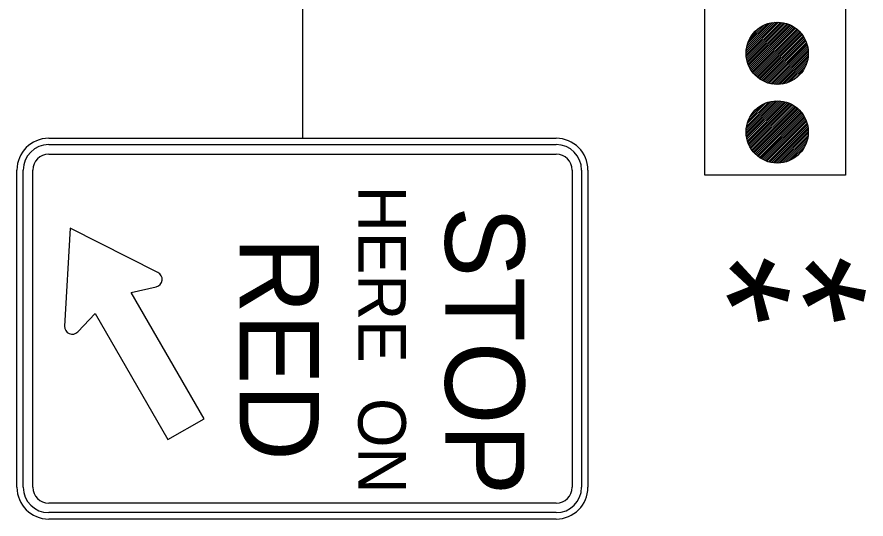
# Model space of a CAD drawing. Extents: x 1927831 to 1930787, y 596452 to 597699.
# Drawn here: x 1928583.7 to 1928664, y 597412.1 to 597459.5 of the extents above; entities that cross this region are included whole.
import ezdxf

# ---------------------------------------------------------------- set-up
doc = ezdxf.new("R2010")
doc.units = 0
for name, color, linetype in [('Default', 7, 'Continuous'), ('P_TC_Signs_Permanent', 7, 'Continuous'), ('R_Border', 7, 'Continuous')]:
    doc.layers.add(name, color=color, linetype=linetype)

msp = doc.modelspace()

# ---------------------------------------------------------------- linework, layer by layer
at = {"layer": 'Default'}
for p, q in [((1928652.681, 597456.132), (1928655.58, 597459.031)), ((1928652.684, 597455.954), (1928655.758, 597459.028)), ((1928652.69, 597456.321), (1928655.391, 597459.022)), ((1928652.697, 597455.785), (1928655.927, 597459.015)), ((1928652.714, 597456.526), (1928655.186, 597458.998)), ((1928652.718, 597455.625), (1928656.087, 597458.994)), ((1928652.746, 597455.473), (1928656.239, 597458.966)), ((1928652.756, 597456.749), (1928654.963, 597458.956)), ((1928652.782, 597455.327), (1928656.385, 597458.93)), ((1928652.823, 597455.188), (1928656.524, 597458.889)), ((1928652.825, 597456.999), (1928654.713, 597458.887)), ((1928652.869, 597455.053), (1928656.659, 597458.842)), ((1928652.921, 597454.925), (1928656.787, 597458.791)), ((1928652.939, 597457.294), (1928654.418, 597458.773)), ((1928652.978, 597454.801), (1928656.911, 597458.734)), ((1928653.04, 597454.681), (1928657.031, 597458.672)), ((1928653.106, 597454.566), (1928657.146, 597458.606)), ((1928653.156, 597457.691), (1928654.021, 597458.556)), ((1928653.176, 597454.456), (1928657.256, 597458.536)), ((1928653.251, 597454.349), (1928657.363, 597458.461)), ((1928653.329, 597454.247), (1928657.465, 597458.383)), ((1928653.412, 597454.149), (1928657.563, 597458.3)), ((1928653.498, 597454.054), (1928657.658, 597458.214)), ((1928653.589, 597453.964), (1928657.748, 597458.123)), ((1928653.683, 597453.877), (1928657.835, 597458.029)), ((1928653.782, 597453.795), (1928657.917, 597457.93)), ((1928653.884, 597453.716), (1928657.996, 597457.828)), ((1928653.99, 597453.642), (1928658.07, 597457.722)), ((1928654.101, 597453.572), (1928658.14, 597457.611)), ((1928654.216, 597453.506), (1928658.206, 597457.496)), ((1928654.335, 597453.444), (1928658.268, 597457.377)), ((1928654.459, 597453.387), (1928658.325, 597457.253)), ((1928654.588, 597453.335), (1928658.377, 597457.124)), ((1928654.722, 597453.289), (1928658.423, 597456.99)), ((1928654.862, 597453.248), (1928658.464, 597456.85)), ((1928655.008, 597453.212), (1928658.5, 597456.704)), ((1928655.16, 597453.184), (1928658.528, 597456.552)), ((1928655.32, 597453.163), (1928658.549, 597456.392)), ((1928655.489, 597453.151), (1928658.561, 597456.223)), ((1928655.667, 597453.148), (1928658.564, 597456.045)), ((1928655.857, 597453.157), (1928658.555, 597455.855)), ((1928656.061, 597453.18), (1928658.532, 597455.651)), ((1928656.285, 597453.223), (1928658.489, 597455.427)), ((1928656.535, 597453.293), (1928658.419, 597455.177)), ((1928656.83, 597453.407), (1928658.305, 597454.882)), ((1928657.229, 597453.625), (1928658.087, 597454.483)), ((1928652.681, 597448.612), (1928655.661, 597451.592)), ((1928652.685, 597448.797), (1928655.476, 597451.588)), ((1928652.689, 597448.439), (1928655.834, 597451.584)), ((1928652.701, 597448.994), (1928655.279, 597451.572)), ((1928652.705, 597448.274), (1928655.998, 597451.568)), ((1928652.73, 597448.118), (1928656.155, 597451.543)), ((1928652.735, 597449.208), (1928655.065, 597451.538)), ((1928652.761, 597447.969), (1928656.304, 597451.512)), ((1928652.791, 597449.445), (1928654.828, 597451.482)), ((1928652.799, 597447.826), (1928656.447, 597451.474)), ((1928652.843, 597447.688), (1928656.584, 597451.43)), ((1928652.881, 597449.717), (1928654.556, 597451.392)), ((1928652.892, 597447.557), (1928656.716, 597451.381)), ((1928652.946, 597447.43), (1928656.843, 597451.327)), ((1928653.005, 597447.308), (1928656.965, 597451.268)), ((1928653.038, 597450.054), (1928654.219, 597451.235)), ((1928653.069, 597447.191), (1928657.082, 597451.204)), ((1928653.137, 597447.078), (1928657.195, 597451.136)), ((1928653.209, 597446.969), (1928657.304, 597451.064)), ((1928653.285, 597446.865), (1928657.408, 597450.988)), ((1928653.365, 597446.764), (1928657.509, 597450.908)), ((1928653.45, 597446.667), (1928657.606, 597450.823)), ((1928653.538, 597446.575), (1928657.698, 597450.735)), ((1928653.63, 597446.486), (1928657.787, 597450.643)), ((1928653.726, 597446.401), (1928657.872, 597450.547)), ((1928653.826, 597446.321), (1928657.952, 597450.446)), ((1928653.931, 597446.244), (1928658.029, 597450.342)), ((1928654.039, 597446.171), (1928658.102, 597450.234)), ((1928654.151, 597446.103), (1928658.17, 597450.122)), ((1928654.268, 597446.039), (1928658.234, 597450.005)), ((1928654.39, 597445.979), (1928658.294, 597449.883)), ((1928654.516, 597445.925), (1928658.308, 597449.716)), ((1928654.647, 597445.875), (1928658.398, 597449.626)), ((1928654.784, 597445.831), (1928658.442, 597449.489)), ((1928654.926, 597445.792), (1928658.481, 597449.347)), ((1928655.075, 597445.76), (1928658.513, 597449.198)), ((1928655.23, 597445.735), (1928658.538, 597449.043)), ((1928655.394, 597445.717), (1928658.556, 597448.879)), ((1928655.566, 597445.709), (1928658.564, 597448.707)), ((1928655.749, 597445.711), (1928658.562, 597448.523)), ((1928655.945, 597445.726), (1928658.547, 597448.328)), ((1928656.157, 597445.757), (1928658.516, 597448.115)), ((1928656.392, 597445.811), (1928658.462, 597447.881)), ((1928656.659, 597445.897), (1928658.376, 597447.614)), ((1928656.986, 597446.043), (1928658.23, 597447.287)), ((1928657.559, 597446.436), (1928657.837, 597446.714))]:
    msp.add_line(p, q, dxfattribs=at)
msp.add_lwpolyline([(1928648.778, 597469.101), (1928662.071, 597469.101), (1928662.071, 597444.566), (1928648.778, 597444.566)], close=True, dxfattribs=at)
for centre in [(1928655.623, 597456.089), (1928655.623, 597448.65)]:
    msp.add_circle(centre, 2.942, dxfattribs=at)
at = {"layer": 'P_TC_Signs_Permanent'}
for p, q in [((1928586.718, 597448.051), (1928634.718, 597448.051)), ((1928586.718, 597447.451), (1928634.718, 597447.451)), ((1928586.718, 597446.551), (1928634.718, 597446.551)), ((1928583.718, 597415.051), (1928583.718, 597445.051)), ((1928584.318, 597415.051), (1928584.318, 597445.051)), ((1928585.218, 597415.051), (1928585.218, 597445.051)), ((1928636.218, 597445.051), (1928636.218, 597415.051)), ((1928637.118, 597445.051), (1928637.118, 597415.051)), ((1928637.718, 597445.051), (1928637.718, 597415.051)), ((1928634.718, 597413.551), (1928586.718, 597413.551)), ((1928634.718, 597412.651), (1928586.718, 597412.651)), ((1928634.718, 597412.051), (1928586.718, 597412.051))]:
    msp.add_line(p, q, dxfattribs=at)
for points in [[(1928597.055, 597435.351), (1928588.733, 597439.55), (1928588.224, 597430.28)], [(1928589.467, 597429.746), (1928591.114, 597431.49), (1928597.997, 597419.567), (1928601.407, 597421.536), (1928594.524, 597433.458), (1928596.893, 597434.007)]]:
    msp.add_lwpolyline(points, dxfattribs=at)
for centre, radius, start, end in [((1928586.718, 597445.051), 3, 90, 180), ((1928634.718, 597445.051), 3, 360, 90), ((1928586.718, 597445.051), 2.4, 90, 180), ((1928634.718, 597445.051), 2.4, 360, 90), ((1928586.718, 597445.051), 1.5, 90, 180), ((1928634.718, 597445.051), 1.5, 360, 90), ((1928596.731, 597434.708), 0.72, 283.03493, 63.22861), ((1928588.943, 597430.24), 0.72, 176.85697, 316.6377), ((1928586.718, 597415.051), 3, 180, 270), ((1928586.718, 597415.051), 2.4, 180, 270), ((1928586.718, 597415.051), 1.5, 180, 270), ((1928634.718, 597415.051), 3, 270, 360), ((1928634.718, 597415.051), 2.4, 270, 360), ((1928634.718, 597415.051), 1.5, 270, 360)]:
    msp.add_arc(centre, radius, start, end, dxfattribs=at)
at = {"layer": 'R_Border'}
msp.add_line((1928610.718, 597465.077), (1928610.718, 597448.051), dxfattribs=at)

# ---------------------------------------------------------------- texts
at = {"layer": 'P_TC_Signs_Permanent'}
for s, height, p in [('HERE  ON', 4.5, (1928615.998, 597443.551)), ('STOP', 7.5, (1928624.218, 597441.614)), ('RED', 7.5, (1928604.778, 597438.721))]:
    msp.add_text(s, height=height, rotation=270, dxfattribs=at).set_placement(p)
at = {"layer": 'R_Border'}
for p in [(1928657.722, 597425.396), (1928664.909, 597425.396)]:
    msp.add_text('*', height=12, rotation=45, dxfattribs=at).set_placement(p)

doc.saveas('drawing.dxf')
